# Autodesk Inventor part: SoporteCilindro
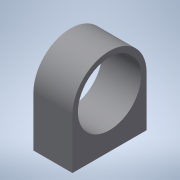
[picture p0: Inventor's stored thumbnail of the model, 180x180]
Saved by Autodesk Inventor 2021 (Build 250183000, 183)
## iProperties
Created: 2021-02
Part Number: SoporteCilindro
Material: Genérico
Document SubType Name: Modeling
Designer: ATOUZA
Density: 1 g/cm^3
Appearance: Valor por defecto
Author: ATOUZA
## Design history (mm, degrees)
sketch "Boceto1"
  geometry: L1 (4.21, 9.241)-(7.675, 15.241) reference; L2 (-2.718, 9.241)-(4.21, 9.241) reference; L3 (-9.646, 9.241)-(-2.718, 9.241) reference; L4 (-13.11, 15.241)-(-9.646, 9.241) reference; L5 (-16.574, 21.241)-(-13.11, 15.241) reference; L6 (-13.11, 27.241)-(-16.574, 21.241) reference; L7 (-9.646, 33.241)-(-13.11, 27.241) reference; L8 (-2.718, 33.241)-(-9.646, 33.241) reference; L9 (4.21, 33.241)-(-2.718, 33.241) reference; L10 (7.675, 27.241)-(4.21, 33.241) reference; L11 (11.139, 21.241)-(7.675, 27.241) reference; L12 (7.675, 15.241)-(11.139, 21.241) reference; L13 (-13.568, 35.333)-(-13.568, 39.333) reference; L14 (-15.568, 135.266)-(-15.568, 5.822); L15 (-2.718, 30.741)-(-15.568, 30.741); L16 (-2.718, 11.741)-(-15.568, 11.741); L17 (-15.568, 30.741)-(-15.568, 11.741); C1 r 8 at (-2.718, 21.241) reference; C2 r 3 at (-2.718, 21.241) reference; C3 r 3 at (-2.718, 21.241); C4 r 8.1 at (-2.718, 21.241); A1 r 9.5 centre (-2.718, 21.241) between (-2.718, 11.741) and (-2.718, 30.741); 1 further point
  constraints: 8 end point, 3 centre point, 3 coincident, 2 perpendicular, 2 point on circle, 2 point on line, 2 tangent, 2 vertical, 1 concentric
  dimensions: "d0" = 16.2 diameter of C4; "d1" = 19 diameter of A1
extrude "Extrusión1" new body sketch "Boceto1" distance "d2" = 10; taper "d3" = 0 deg
node "Sólido1"
node "Referencia5"
node "Referencia6"
node "Referencia7"
node "Referencia8"
node "Referencia9"
node "Referencia10"
node "Referencia11"
node "Referencia12"
node "Referencia13"
node "Referencia14"
node "Referencia15"
node "Referencia16"
node "Referencia17"
node "Referencia18"
node "Referencia19"
